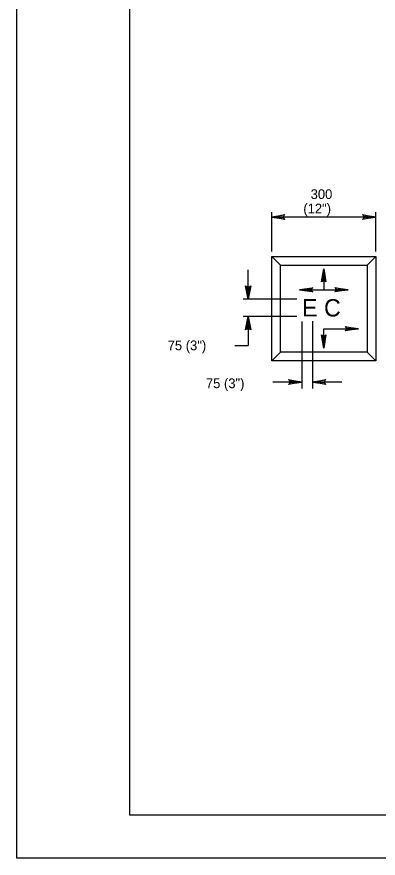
# Model space of a CAD drawing. Extents: x 638448 to 639352, y 297825 to 299013.
# Drawn here: x 638447.7 to 638572.7, y 297825.3 to 298115.9 of the extents above; entities that cross this region are included whole.
import ezdxf

# ---------------------------------------------------------------- set-up
doc = ezdxf.new("R2010")
doc.units = 0
for name, color, linetype in [('1', 7, 'Continuous'), ('2', 7, 'Continuous'), ('3', 7, 'Continuous'), ('PLT-BNDY', 7, 'Continuous')]:
    doc.layers.add(name, color=color, linetype=linetype)

msp = doc.modelspace()

# ---------------------------------------------------------------- linework, layer by layer
at = {"layer": '1'}
msp.add_lwpolyline([(639272.65, 297840.29), (639272.65, 298404.29), (638486.65, 298404.29), (638486.65, 297840.29), (639272.65, 297840.29), (639272.65, 297866.65), (639072.65, 297866.65), (639072.65, 297931.33), (639272.65, 297931.33), (639272.65, 297960.29), (639072.65, 297960.29), (639072.65, 297840.29), (639151.45, 297840.29), (639151.45, 297866.65), (639151.45, 297840.29), (639228.45, 297840.29), (639228.45, 297866.65), (639228.45, 297854.33), (639272.65, 297854.33)], dxfattribs=at)
at = {"layer": '2'}
for p, q in [((638535.83, 298034.79), (638535.83, 298048.39)), ((638563.27, 298046.71), (638535.83, 298046.71)), ((638571.83, 298046.71), (638563.27, 298046.71)), ((638571.83, 298034.79), (638571.83, 298048.39)), ((638538.83, 298030.11), (638535.83, 298033.11)), ((638568.83, 298030.11), (638571.83, 298033.11)), ((638553.83, 298028.87), (638553.83, 298021.6)), ((638527.69, 298018.36), (638527.69, 298028.44)), ((638545.43, 298021.6), (638562.23, 298021.6)), ((638544.57, 298018.36), (638526.01, 298018.36)), ((638544.57, 298012.34), (638526.01, 298012.34)), ((638546.25, 298010.66), (638546.25, 297987.48)), ((638549.99, 298010.78), (638549.99, 297987.48)), ((638553.83, 298008.15), (638565.83, 298008.15)), ((638553.83, 298001.42), (638553.83, 298008.15)), ((638538.83, 298000.11), (638535.83, 297997.11)), ((638568.83, 298000.11), (638571.83, 297997.11)), ((638546.25, 297989.72), (638536.17, 297989.72)), ((638560.07, 297989.72), (638549.99, 297989.72))]:
    msp.add_line(p, q, dxfattribs=at)
for points in [[(638540.19, 298046.05), (638540.02, 298046.43), (638535.83, 298046.71), (638540.19, 298046.05), (638540.41, 298045.82), (638535.83, 298046.71), (638540.02, 298046.96), (638540.17, 298047.33), (638535.83, 298046.71), (638540.41, 298047.58), (638540.17, 298047.33)], [(638567.47, 298047.36), (638567.63, 298046.98), (638571.83, 298046.71), (638567.47, 298047.36), (638567.25, 298047.59), (638571.83, 298046.71), (638567.64, 298046.46), (638567.48, 298046.08), (638571.83, 298046.71), (638567.25, 298045.83), (638567.48, 298046.08)], [(638571.83, 297997.11), (638535.83, 297997.11), (638535.83, 298033.11), (638571.83, 298033.11), (638571.83, 297997.11)], [(638568.83, 298000.11), (638538.83, 298000.11), (638538.83, 298030.11), (638568.83, 298030.11), (638568.83, 298000.11)], [(638553.28, 298024.51), (638553.6, 298024.68), (638553.83, 298028.87), (638553.28, 298024.51), (638553.09, 298024.29), (638553.83, 298028.87), (638554.04, 298024.68), (638554.35, 298024.53), (638553.83, 298028.87), (638554.56, 298024.29), (638554.35, 298024.53)], [(638528.34, 298022.71), (638527.96, 298022.55), (638527.69, 298018.36), (638528.34, 298022.71), (638528.57, 298022.94), (638527.69, 298018.36), (638527.44, 298022.55), (638527.06, 298022.7), (638527.69, 298018.36), (638526.81, 298022.94), (638527.06, 298022.7)], [(638549.79, 298021.05), (638549.62, 298021.37), (638545.43, 298021.6), (638549.79, 298021.05), (638550.01, 298020.86), (638545.43, 298021.6), (638549.62, 298021.8), (638549.77, 298022.12), (638545.43, 298021.6), (638550.01, 298022.33), (638549.77, 298022.12)], [(638557.87, 298022.14), (638558.03, 298021.83), (638562.23, 298021.6), (638557.87, 298022.14), (638557.65, 298022.34), (638562.23, 298021.6), (638558.03, 298021.39), (638557.88, 298021.08), (638562.23, 298021.6), (638557.65, 298020.87), (638557.88, 298021.08)], [(638527.03, 298007.98), (638527.41, 298008.14), (638527.69, 298012.34), (638527.03, 298007.98), (638526.8, 298007.75), (638527.69, 298012.34), (638527.94, 298008.14), (638528.31, 298007.99), (638527.69, 298012.34), (638528.56, 298007.75), (638528.31, 298007.99)], [(638527.69, 298012.34), (638527.69, 298002.39)], [(638561.47, 298008.7), (638561.63, 298008.38), (638565.83, 298008.15), (638561.47, 298008.7), (638561.25, 298008.89), (638565.83, 298008.15), (638561.63, 298007.94), (638561.48, 298007.63), (638565.83, 298008.15), (638561.25, 298007.42), (638561.48, 298007.63)], [(638554.37, 298005.78), (638554.06, 298005.62), (638553.83, 298001.42), (638554.37, 298005.78), (638554.57, 298006), (638553.83, 298001.42), (638553.62, 298005.62), (638553.31, 298005.77), (638553.83, 298001.42), (638553.1, 298006), (638553.31, 298005.77)], [(638523.03, 298002.39), (638527.69, 298002.39)], [(638541.89, 297990.38), (638542.05, 297990), (638546.25, 297989.72), (638541.89, 297990.38), (638541.67, 297990.61), (638546.25, 297989.72), (638542.06, 297989.47), (638541.9, 297989.1), (638546.25, 297989.72), (638541.67, 297988.85), (638541.9, 297989.1)], [(638554.35, 297989.07), (638554.18, 297989.45), (638549.99, 297989.72), (638554.35, 297989.07), (638554.57, 297988.84), (638549.99, 297989.72), (638554.18, 297989.97), (638554.33, 297990.35), (638549.99, 297989.72), (638554.57, 297990.6), (638554.33, 297990.35)]]:
    msp.add_lwpolyline(points, dxfattribs=at)
at = {"layer": 'PLT-BNDY'}
msp.add_lwpolyline([(638447.65, 298419.29), (639288.65, 298419.29), (639288.65, 297825.29), (638447.65, 297825.29)], close=True, dxfattribs=at)

# ---------------------------------------------------------------- texts
at = {"layer": '3'}
for s, height, p in [('300', 3.36, (638549.3, 298052.95)), ('(12")', 3.36, (638546.77, 298047.99)), ('E C', 6, (638546.34, 298012.38)), ('75 (3")', 3.36, (638499.85, 298000.72)), ('75 (3")', 3.36, (638513.07, 297987.62))]:
    msp.add_text(s, height=height, dxfattribs=at).set_placement(p)

doc.saveas('drawing.dxf')
